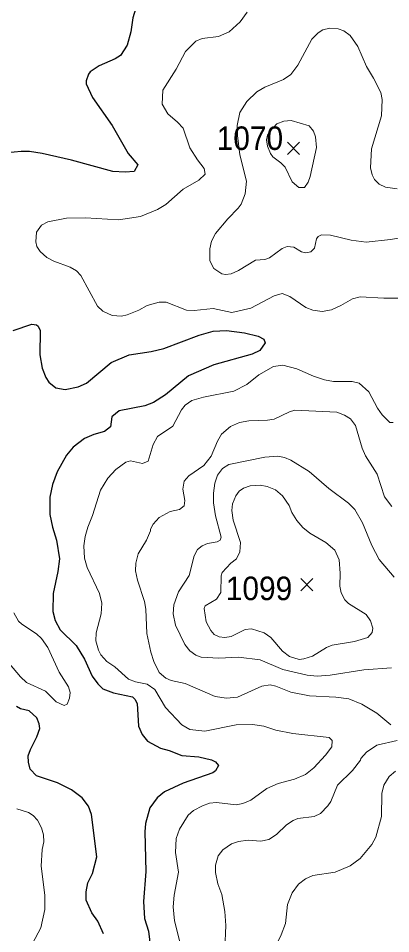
# Model space of a CAD drawing. Extents: x 265 to 291.4, y 7731.5 to 7759.6.
# Drawn here: x 276.962 to 278.229, y 7740.103 to 7743.215 of the extents above; entities that cross this region are included whole.
import ezdxf
from ezdxf.enums import TextEntityAlignment as Align

# ---------------------------------------------------------------- set-up
doc = ezdxf.new("R2010")
doc.units = 0
doc.header["$LTSCALE"] = 0.032
for name, color, linetype, lineweight in [('1', 7, 'Continuous', 25), ('2', 7, 'Continuous', 13), ('21', 7, 'Continuous', 25), ('61', 7, 'Continuous', 13)]:
    doc.layers.add(name, color=color, linetype=linetype, lineweight=lineweight)

msp = doc.modelspace()

# ---------------------------------------------------------------- linework, layer by layer
at = {"layer": '1'}
for points in [[(277.3848, 7743.2942), (277.3657, 7743.264), (277.3514, 7743.2162), (277.3442, 7743.1685), (277.3323, 7743.1239), (277.3092, 7743.0889), (277.2909, 7743.077), (277.2368, 7743.0531), (277.2058, 7743.0332), (277.2002, 7743.0253), (277.1931, 7743.003), (277.1931, 7742.9927), (277.2137, 7742.9458), (277.2814, 7742.8503), (277.3354, 7742.7556), (277.3689, 7742.7174), (277.3562, 7742.6944), (277.3259, 7742.692), (277.283, 7742.6944), (277.143, 7742.7333), (277.0427, 7742.7556), (276.9998, 7742.762), (276.9711, 7742.7628), (276.9234, 7742.758)], [(276.9441, 7742.1542), (277.0077, 7742.1749), (277.0236, 7742.1733), (277.0292, 7742.1685), (277.0363, 7742.1542), (277.0348, 7742.0707), (277.0427, 7742.0262), (277.0554, 7741.9944), (277.0658, 7741.9784), (277.0897, 7741.9593), (277.1207, 7741.953), (277.1652, 7741.9625), (277.1939, 7741.9752), (277.2774, 7742.0453), (277.3387, 7742.0707), (277.4134, 7742.0826), (277.4564, 7742.093), (277.5773, 7742.1383), (277.625, 7742.151), (277.6696, 7742.1534), (277.7316, 7742.1463), (277.7778, 7742.1351), (277.7968, 7742.124), (277.8016, 7742.1121), (277.7833, 7742.0858), (277.7571, 7742.0739), (277.6266, 7742.0373), (277.5407, 7741.9999), (277.4627, 7741.9355), (277.4214, 7741.9092), (277.3928, 7741.8973), (277.3052, 7741.8806), (277.2798, 7741.8599), (277.275, 7741.8265), (277.2551, 7741.8106), (277.2193, 7741.8002), (277.1875, 7741.7867), (277.1485, 7741.7573), (277.1262, 7741.7303), (277.0936, 7741.673), (277.0777, 7741.63), (277.069, 7741.5871), (277.069, 7741.5282), (277.0777, 7741.4852), (277.092, 7741.4407), (277.1016, 7741.3771), (277.096, 7741.3341), (277.0801, 7741.2593), (277.0793, 7741.1989), (277.0873, 7741.1686), (277.104, 7741.1368), (277.1581, 7741.0827), (277.1875, 7741.0366), (277.2129, 7740.9793), (277.232, 7740.9523), (277.2495, 7740.9356)], [(277.2495, 7740.9356), (277.2862, 7740.922), (277.3498, 7740.9085), (277.3578, 7740.9005), (277.3657, 7740.8855), (277.3705, 7740.8091), (277.3832, 7740.7804)], [(277.2519, 7740.1027), (277.232, 7740.1457), (277.2121, 7740.1743), (277.1923, 7740.2172), (277.1923, 7740.2459), (277.1986, 7740.2761), (277.2145, 7740.3079), (277.2289, 7740.3652), (277.2106, 7740.5084), (277.2002, 7740.537), (277.1795, 7740.5657), (277.1422, 7740.5927), (277.0952, 7740.6158), (277.0236, 7740.6404), (277.0021, 7740.6627), (276.9966, 7740.6866), (276.9958, 7740.708), (277.0029, 7740.7295), (277.0252, 7740.7725), (277.0348, 7740.8011), (277.0332, 7740.817), (277.0252, 7740.8369), (276.9982, 7740.8608), (276.9696, 7740.8679), (276.9552, 7740.8759)], [(277.3832, 7740.7804), (277.4015, 7740.7574), (277.4453, 7740.7343), (277.4755, 7740.7263), (277.5184, 7740.7096), (277.5757, 7740.7049), (277.6187, 7740.6945), (277.633, 7740.6881), (277.6425, 7740.6754), (277.633, 7740.6571), (277.6234, 7740.65), (277.5232, 7740.615), (277.4596, 7740.5855), (277.4341, 7740.5648), (277.4094, 7740.5307), (277.3943, 7740.4782), (277.3919, 7740.4495), (277.3951, 7740.3143), (277.388, 7740.2125), (277.3911, 7740.1552), (277.4047, 7740.1122), (277.4118, 7740.055)]]:
    msp.add_lwpolyline(points, dxfattribs=at)
at = {"layer": '2'}
for points in [[(277.0236, 7742.4876), (277.0403, 7742.5114), (277.0618, 7742.5233), (277.1255, 7742.5361), (277.1907, 7742.5369), (277.3021, 7742.5305), (277.3776, 7742.5408), (277.4357, 7742.5647), (277.4635, 7742.5822), (277.5232, 7742.6347), (277.5765, 7742.6649), (277.5972, 7742.6856), (277.594, 7742.7047), (277.5709, 7742.7342), (277.5455, 7742.7747), (277.5224, 7742.8415), (277.5033, 7742.8622), (277.4707, 7742.8901), (277.4516, 7742.9235), (277.454, 7742.9712), (277.4985, 7743.042), (277.5304, 7743.1017), (277.5654, 7743.1375), (277.5869, 7743.1462), (277.6425, 7743.1534), (277.6791, 7743.1693), (277.7165, 7743.2027), (277.7404, 7743.2361)], [(278.2503, 7742.6355), (278.2105, 7742.6411), (278.189, 7742.6514), (278.1739, 7742.6673), (278.1652, 7742.6832), (278.1596, 7742.7071), (278.1628, 7742.7708), (278.197, 7742.8837), (278.2002, 7742.9394), (278.1946, 7742.9633), (278.1707, 7743.011), (278.1461, 7743.0508), (278.1174, 7743.1192), (278.0904, 7743.1566), (278.0689, 7743.1725), (278.0498, 7743.1788), (278.0212, 7743.1812), (277.9973, 7743.1756), (277.9814, 7743.1653), (277.9599, 7743.1438), (277.9122, 7743.0555), (277.8891, 7743.0245), (277.8645, 7743.007), (277.8, 7742.9815), (277.773, 7742.9648), (277.7388, 7742.9322), (277.7157, 7742.8948), (277.7062, 7742.8511), (277.7072, 7742.8167), (277.7151, 7742.7511), (277.7377, 7742.661), (277.734, 7742.618), (277.7197, 7742.583), (277.7101, 7742.5695), (277.6743, 7742.5337), (277.6322, 7742.4836), (277.6195, 7742.4573), (277.6131, 7742.4319), (277.6139, 7742.3905), (277.6274, 7742.3643), (277.6537, 7742.3467), (277.6664, 7742.3444), (277.6855, 7742.3467), (277.7109, 7742.3579), (277.7682, 7742.3929), (277.8, 7742.3953), (277.8159, 7742.4008), (277.8589, 7742.4327), (277.8764, 7742.439), (277.8995, 7742.4374), (277.9249, 7742.4207), (277.9385, 7742.4175), (277.9575, 7742.4207), (277.9695, 7742.4335), (277.9766, 7742.4653), (277.9814, 7742.4732), (277.9933, 7742.4788), (278.0244, 7742.478), (278.0944, 7742.4605), (278.1453, 7742.4541), (278.228, 7742.4629), (278.3553, 7742.4844)], [(277.1382, 7742.369), (277.0825, 7742.3897), (277.0594, 7742.4016), (277.0364, 7742.4223), (277.0252, 7742.4398), (277.0212, 7742.4557), (277.0236, 7742.4876)], [(278.2614, 7742.264), (278.2057, 7742.2632), (278.1246, 7742.268), (278.0991, 7742.2616), (278.0594, 7742.2386), (278.0275, 7742.2242), (277.9957, 7742.2187), (277.9639, 7742.2226), (277.94, 7742.2322), (277.8859, 7742.2696), (277.8597, 7742.2791), (277.8319, 7742.272), (277.7523, 7742.2298), (277.6887, 7742.2155), (277.625, 7742.2282), (277.5598, 7742.2218), (277.5343, 7742.2234), (277.4643, 7742.2497), (277.4405, 7742.2505), (277.4007, 7742.2386), (277.3721, 7742.2226), (277.3323, 7742.2067), (277.3132, 7742.2028), (277.2814, 7742.2051), (277.2496, 7742.2195), (277.2313, 7742.237), (277.174, 7742.3412), (277.1597, 7742.3563), (277.1382, 7742.369)], [(277.2384, 7741.2593), (277.1963, 7741.3484), (277.1867, 7741.3802), (277.1851, 7741.4216), (277.1891, 7741.4534), (277.1978, 7741.4852), (277.2146, 7741.525), (277.2416, 7741.6109), (277.2663, 7741.6523), (277.2933, 7741.6817), (277.3275, 7741.7064), (277.3434, 7741.7111), (277.3848, 7741.7016), (277.4031, 7741.7096), (277.4206, 7741.7668), (277.4357, 7741.7931), (277.4874, 7741.8289), (277.5168, 7741.8846), (277.5296, 7741.8997), (277.5526, 7741.9156), (277.5916, 7741.9275), (277.695, 7741.9474), (277.7396, 7741.9697), (277.7801, 7742.0031), (277.8303, 7742.0317), (277.8621, 7742.0357), (277.9098, 7742.0238), (277.9655, 7741.9983), (278.0037, 7741.9856), (278.0339, 7741.9808), (278.0976, 7741.98), (278.1214, 7741.9745), (278.1548, 7741.945), (278.1842, 7741.8894), (278.1994, 7741.8671), (278.2256, 7741.8416), (278.2367, 7741.8416)], [(278.232, 7741.556), (278.2081, 7741.5887), (278.1827, 7741.665), (278.1429, 7741.7279), (278.1317, 7741.7541), (278.1087, 7741.8305), (278.092, 7741.8536), (278.0713, 7741.8663), (278.045, 7741.8758), (277.9027, 7741.883), (277.8844, 7741.8774), (277.8327, 7741.8527), (277.8096, 7741.8488), (277.7459, 7741.8472), (277.7141, 7741.8416), (277.6839, 7741.8273), (277.6529, 7741.8011), (277.6393, 7741.778), (277.6179, 7741.7271), (277.5924, 7741.6952), (277.5415, 7741.6602), (277.5264, 7741.6412), (277.5216, 7741.6141), (277.5288, 7741.5759), (277.5264, 7741.5576), (277.5105, 7741.5449), (277.4787, 7741.5385), (277.4405, 7741.5178), (277.4206, 7741.4956), (277.411, 7741.4789), (277.411, 7741.4725), (277.3983, 7741.4407), (277.3697, 7741.3946), (277.3617, 7741.3627), (277.3609, 7741.3373), (277.3673, 7741.3055), (277.3911, 7741.2323), (277.3951, 7741.2068), (277.3991, 7741.1241), (277.4126, 7741.0605), (277.423, 7741.0286), (277.4413, 7740.9912), (277.4635, 7740.9721), (277.4818, 7740.9642), (277.5296, 7740.9539), (277.6314, 7740.9101), (277.6696, 7740.9045), (277.7078, 7740.9069), (277.7905, 7740.9443), (277.8191, 7740.9491), (277.8382, 7740.9451), (277.8891, 7740.9244), (277.9528, 7740.9117), (278.0419, 7740.9069), (278.0864, 7740.9014), (278.131, 7740.8839), (278.1819, 7740.8528), (278.2288, 7740.8131)], [(278.2312, 7741.0071), (278.1373, 7741), (278.0228, 7740.9817), (277.9782, 7740.9793), (277.9448, 7740.9825), (277.8621, 7741.0016), (277.7849, 7741.0342), (277.7109, 7741.0429), (277.6441, 7741.0398), (277.5837, 7741.0429), (277.5662, 7741.0501), (277.5455, 7741.0652), (277.5288, 7741.0859), (277.4961, 7741.1527), (277.489, 7741.1909), (277.4906, 7741.2211), (277.5065, 7741.2657), (277.5431, 7741.3214), (277.5598, 7741.3882), (277.5709, 7741.4097), (277.5868, 7741.4224), (277.6051, 7741.4303), (277.6378, 7741.4351), (277.6481, 7741.4407), (277.6521, 7741.4518), (277.633, 7741.5234), (277.6258, 7741.568), (277.6258, 7741.6014), (277.6306, 7741.6348), (277.6394, 7741.6626), (277.6569, 7741.6849), (277.6775, 7741.6984), (277.8, 7741.7231), (277.8446, 7741.7263), (277.8669, 7741.7223), (277.8891, 7741.7135), (277.9512, 7741.6746), (278.018, 7741.6165), (278.0848, 7741.5672), (278.1063, 7741.5457), (278.1333, 7741.4996), (278.1644, 7741.4232), (278.189, 7741.3755), (278.2407, 7741.315)], [(277.2424, 7741.0509), (277.2344, 7741.0668), (277.2257, 7741.0986), (277.2265, 7741.1265), (277.244, 7741.1909), (277.2456, 7741.2275), (277.2384, 7741.2593)], [(276.9465, 7741.1941), (276.9624, 7741.1663), (276.9743, 7741.1551), (277.0236, 7741.1225), (277.0411, 7741.1066), (277.0618, 7741.0764), (277.1008, 7740.992), (277.1326, 7740.9427), (277.1382, 7740.9236), (277.1358, 7740.9045), (277.1278, 7740.8831), (277.1183, 7740.8791), (277.0905, 7740.8918), (277.0547, 7740.9284), (276.9894, 7740.9578), (276.9695, 7740.9761), (276.9314, 7741.0207)], [(277.5113, 7740.0756), (277.493, 7740.1472), (277.489, 7740.195), (277.4922, 7740.2347), (277.5073, 7740.3127), (277.4969, 7740.3795), (277.4985, 7740.4273), (277.5097, 7740.4591), (277.5399, 7740.506), (277.5582, 7740.5219), (277.5884, 7740.5386), (277.6123, 7740.5466), (277.6362, 7740.5497), (277.703, 7740.5418), (277.7253, 7740.5458), (277.7523, 7740.5569), (277.8072, 7740.5975), (277.8462, 7740.6142), (277.9019, 7740.6285), (277.9385, 7740.6444), (277.9671, 7740.6675), (278.0069, 7740.7104), (278.0283, 7740.7383), (278.0299, 7740.7606), (278.0196, 7740.7701), (277.8955, 7740.7844), (277.8382, 7740.7955), (277.7976, 7740.8083), (277.7587, 7740.8146), (277.703, 7740.813), (277.5964, 7740.7916), (277.5455, 7740.7971), (277.5184, 7740.813), (277.4627, 7740.8727), (277.4261, 7740.934), (277.4007, 7740.9515), (277.3609, 7740.9594), (277.3371, 7740.9682), (277.2901, 7741.0111), (277.2631, 7741.0286), (277.2424, 7741.0509)], [(278.2503, 7740.7606), (278.1819, 7740.7438), (278.1469, 7740.72)], [(278.1469, 7740.72), (278.127, 7740.6993), (278.1254, 7740.6929), (278.0991, 7740.6579), (278.0482, 7740.6078), (278.0251, 7740.5529), (278.0148, 7740.5378)], [(277.9385, 7740.2896), (277.9639, 7740.3008), (278.0403, 7740.3127), (278.0912, 7740.3342), (278.1246, 7740.3596), (278.1644, 7740.4066), (278.1779, 7740.432), (278.197, 7740.502), (278.1986, 7740.58), (278.2049, 7740.6086), (278.2232, 7740.6373), (278.2447, 7740.6563)], [(276.9568, 7740.5275), (276.9966, 7740.5155), (277.0125, 7740.5052), (277.0276, 7740.4893), (277.0411, 7740.4638), (277.0475, 7740.44), (277.0491, 7740.4161), (277.0435, 7740.3891), (277.0395, 7740.3334), (277.0515, 7740.2347), (277.0523, 7740.1854), (277.0387, 7740.1234), (276.9815, 7740.0168), (276.9202, 7739.9468)], [(278.0148, 7740.5378), (277.9901, 7740.5124), (277.9687, 7740.502), (277.913, 7740.4949), (277.8971, 7740.4885), (277.874, 7740.4734), (277.8406, 7740.4408), (277.8136, 7740.4233), (277.7873, 7740.4177), (277.7443, 7740.4209), (277.7109, 7740.4169), (277.6871, 7740.4089), (277.6576, 7740.3883), (277.6417, 7740.3684), (277.6322, 7740.3366), (277.6322, 7740.3111), (277.6401, 7740.2729), (277.6537, 7740.2363), (277.664, 7740.1791), (277.668, 7740.1313), (277.6648, 7740.0518)], [(277.8231, 7740.0311), (277.8565, 7740.0995), (277.8708, 7740.1377), (277.8772, 7740.2029), (277.8931, 7740.2427), (277.9154, 7740.2713), (277.9385, 7740.2896)]]:
    msp.add_lwpolyline(points, dxfattribs=at)
for points in [[(277.8279, 7742.7444), (277.8193, 7742.755), (277.8093, 7742.7809), (277.8067, 7742.8015), (277.8093, 7742.8174), (277.8173, 7742.8307), (277.8414, 7742.8567), (277.8653, 7742.8654), (277.8899, 7742.8678), (277.9512, 7742.8495), (277.9655, 7742.8312), (277.9726, 7742.8121), (277.9758, 7742.7755), (277.9551, 7742.6769), (277.948, 7742.6578), (277.9353, 7742.6395), (277.9162, 7742.6395), (277.8939, 7742.6586), (277.8692, 7742.7087), (277.8549, 7742.7238)], [(277.8922, 7741.5348), (277.8828, 7741.5584), (277.8605, 7741.5918), (277.8366, 7741.6117), (277.808, 7741.6237), (277.7841, 7741.6284), (277.7507, 7741.626), (277.7284, 7741.6181), (277.7133, 7741.6078), (277.7022, 7741.5918), (277.691, 7741.5648), (277.6879, 7741.5425), (277.6926, 7741.5091), (277.7181, 7741.4327), (277.7157, 7741.4009), (277.7038, 7741.3778), (277.6847, 7741.3627), (277.6553, 7741.3317), (277.6521, 7741.3198), (277.6513, 7741.2633), (277.6362, 7741.241), (277.598, 7741.2179), (277.594, 7741.2084), (277.6004, 7741.1639), (277.6171, 7741.1336), (277.6282, 7741.1201), (277.6449, 7741.1122), (277.6648, 7741.1098), (277.6855, 7741.1137), (277.7332, 7741.1376), (277.7555, 7741.14), (277.7984, 7741.1265), (277.8207, 7741.1098), (277.8605, 7741.0636), (277.8844, 7741.0453), (277.9178, 7741.0358), (277.9337, 7741.0374), (277.9623, 7741.0469), (278.01, 7741.0764), (278.0291, 7741.0843), (278.1055, 7741.0962), (278.1508, 7741.1106), (278.1652, 7741.1273), (278.1683, 7741.1416), (278.1604, 7741.1671), (278.1453, 7741.1885), (278.0848, 7741.2259), (278.0729, 7741.2378), (278.0601, 7741.2625), (278.0554, 7741.2848), (278.057, 7741.3293), (278.0538, 7741.3739), (278.0387, 7741.4073), (278.0085, 7741.4335), (277.9536, 7741.4653), (277.9297, 7741.4844), (277.909, 7741.5083)]]:
    msp.add_lwpolyline(points, close=True, dxfattribs=at)
at = {"layer": '21'}
for p, q in [((277.8774, 7742.7936), (277.9186, 7742.7524)), ((277.9186, 7742.7936), (277.8774, 7742.7524)), ((277.9224, 7741.3105), (277.9636, 7741.2693)), ((277.9636, 7741.3105), (277.9224, 7741.2693))]:
    msp.add_line(p, q, dxfattribs=at)

# ---------------------------------------------------------------- texts
at = {"layer": '61', "width": 0.95}
for s, p in [('1070', (277.7496, 7742.7675)), ('1099', (277.7807, 7741.2372))]:
    msp.add_text(s, height=0.08, dxfattribs=at).set_placement(p, align=Align.CENTER)

doc.saveas('drawing.dxf')
